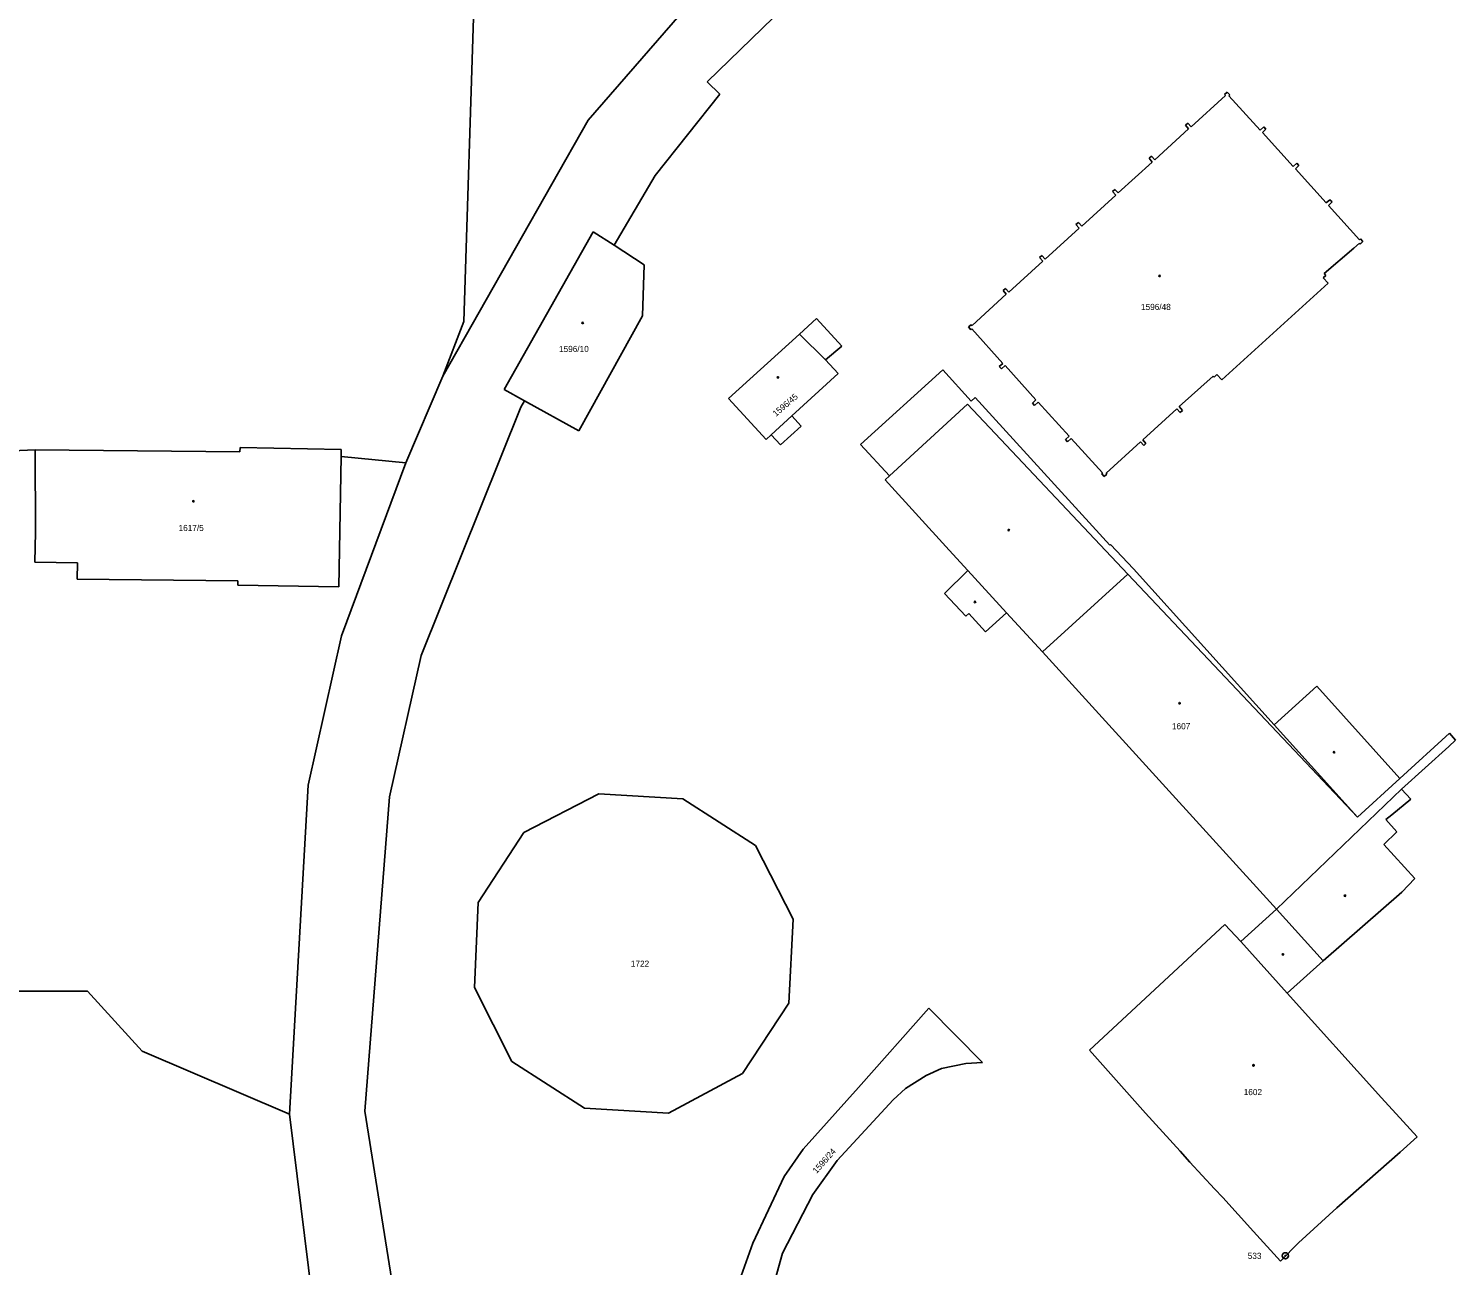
# Model space of a CAD drawing. Extents: x -762761 to -760936, y -1154749 to -1152377.
# Drawn here: x -762540.2 to -762366.3, y -1152807.9 to -1152657.2 of the extents above; entities that cross this region are included whole.
import ezdxf

# ---------------------------------------------------------------- set-up
doc = ezdxf.new("R2010")
doc.units = 0
for name, color, linetype in [('NTL_VÝŠKA', 7, 'Continuous'), ('NTL_ZNAČKA', 7, 'Continuous'), ('NTL_ČÍSLO', 7, 'Continuous'), ('PKO_VÝŠKA', 7, 'Continuous'), ('PKO_ČÍSLO', 7, 'Continuous'), ('PZS_POL_ČÍSLO', 7, 'Continuous'), ('ZP_KÓTY', 7, 'Continuous')]:
    doc.layers.add(name, color=color, linetype=linetype)

msp = doc.modelspace()

# ---------------------------------------------------------------- linework, layer by layer
at = {"layer": 'NTL_VÝŠKA'}
for p, q in [((-762446.26, -1152694.38), (-762443.07, -1152697.52)), ((-762425.8, -1152702.94), (-762435.29, -1152711.67)), ((-762425.8, -1152702.94), (-762406.26, -1152723.62)), ((-762447.19, -1152704.36), (-762449.7, -1152706.66)), ((-762425.74, -1152723.19), (-762421.03, -1152728.33)), ((-762416.67, -1152733.1), (-762406.26, -1152723.62)), ((-762406.26, -1152723.62), (-762378.27, -1152753.23)), ((-762378.27, -1152753.23), (-762388.45, -1152741.99)), ((-762373.11, -1152748.52), (-762378.27, -1152753.23)), ((-762388.13, -1152764.44), (-762372.91, -1152749.82)), ((-762382.45, -1152770.73), (-762388.13, -1152764.44))]:
    msp.add_line(p, q, dxfattribs=at)
at = {"layer": 'NTL_ZNAČKA'}
for p, q in [((-762483.9, -1152590.32), (-762487.15, -1152692.86)), ((-762452.83, -1152646.28), (-762472.01, -1152668.31)), ((-762449.4, -1152655.83), (-762457.48, -1152663.67)), ((-762457.48, -1152663.67), (-762455.94, -1152665.15)), ((-762455.94, -1152665.15), (-762463.84, -1152675.06)), ((-762394.37, -1152665.32), (-762398.54, -1152669.12)), ((-762394.14, -1152664.93), (-762394.47, -1152665.21)), ((-762394.47, -1152665.21), (-762394.37, -1152665.32)), ((-762393.84, -1152665.25), (-762394.14, -1152664.93)), ((-762393.95, -1152665.35), (-762393.84, -1152665.25)), ((-762390.13, -1152669.53), (-762393.95, -1152665.35)), ((-762472.01, -1152668.31), (-762489.68, -1152699.53)), ((-762398.85, -1152669.38), (-762402.98, -1152673.15)), ((-762398.95, -1152668.69), (-762399.24, -1152668.93)), ((-762399.24, -1152668.93), (-762398.85, -1152669.38)), ((-762398.54, -1152669.12), (-762398.95, -1152668.69)), ((-762389.69, -1152669.13), (-762390.13, -1152669.53)), ((-762389.87, -1152669.82), (-762389.43, -1152669.41)), ((-762389.43, -1152669.41), (-762389.69, -1152669.13)), ((-762386.12, -1152673.97), (-762389.87, -1152669.82)), ((-762403.38, -1152672.72), (-762403.67, -1152672.96)), ((-762403.67, -1152672.96), (-762403.29, -1152673.42)), ((-762402.98, -1152673.15), (-762403.38, -1152672.72)), ((-762403.29, -1152673.42), (-762407.42, -1152677.19)), ((-762385.67, -1152673.58), (-762386.12, -1152673.97)), ((-762385.85, -1152674.27), (-762385.41, -1152673.86)), ((-762382.08, -1152678.41), (-762385.85, -1152674.27)), ((-762385.41, -1152673.86), (-762385.67, -1152673.58)), ((-762463.84, -1152675.06), (-762468.82, -1152683.56)), ((-762407.73, -1152677.45), (-762411.87, -1152681.22)), ((-762407.83, -1152676.76), (-762408.12, -1152677)), ((-762408.12, -1152677), (-762407.73, -1152677.45)), ((-762407.42, -1152677.19), (-762407.83, -1152676.76)), ((-762381.65, -1152678.01), (-762382.08, -1152678.41)), ((-762381.38, -1152678.29), (-762381.65, -1152678.01)), ((-762381.81, -1152678.71), (-762381.38, -1152678.29)), ((-762378.02, -1152682.9), (-762381.81, -1152678.71)), ((-762412.18, -1152681.48), (-762416.32, -1152685.25)), ((-762412.28, -1152680.79), (-762412.57, -1152681.04)), ((-762412.57, -1152681.04), (-762412.18, -1152681.48)), ((-762411.87, -1152681.22), (-762412.28, -1152680.79)), ((-762482.24, -1152701.14), (-762471.39, -1152681.91)), ((-762471.39, -1152681.91), (-762468.82, -1152683.56)), ((-762378.74, -1152683.92), (-762378.04, -1152683.31)), ((-762378.04, -1152683.31), (-762377.95, -1152683.41)), ((-762377.9, -1152682.8), (-762378.02, -1152682.9)), ((-762377.95, -1152683.41), (-762377.62, -1152683.11)), ((-762377.62, -1152683.11), (-762377.9, -1152682.8)), ((-762468.82, -1152683.56), (-762465.15, -1152685.93)), ((-762416.72, -1152684.81), (-762417.02, -1152685.06)), ((-762417.02, -1152685.06), (-762416.63, -1152685.52)), ((-762416.32, -1152685.25), (-762416.72, -1152684.81)), ((-762382.33, -1152687.01), (-762378.74, -1152683.92)), ((-762465.15, -1152685.93), (-762465.37, -1152692.18)), ((-762416.63, -1152685.52), (-762420.76, -1152689.28)), ((-762394.82, -1152699.95), (-762381.86, -1152688.18)), ((-762382.47, -1152687.54), (-762382.13, -1152687.24)), ((-762381.86, -1152688.18), (-762382.47, -1152687.54)), ((-762382.13, -1152687.24), (-762382.33, -1152687.01)), ((-762421.07, -1152689.54), (-762425.23, -1152693.35)), ((-762421.16, -1152688.83), (-762421.46, -1152689.09)), ((-762421.46, -1152689.09), (-762421.07, -1152689.54)), ((-762420.76, -1152689.28), (-762421.16, -1152688.83)), ((-762487.15, -1152692.86), (-762489.68, -1152699.53)), ((-762465.37, -1152692.18), (-762473.14, -1152706.19)), ((-762446.26, -1152694.38), (-762444.18, -1152692.48)), ((-762444.18, -1152692.48), (-762441.09, -1152695.84)), ((-762425.34, -1152693.24), (-762425.67, -1152693.52)), ((-762425.67, -1152693.52), (-762425.39, -1152693.85)), ((-762425.39, -1152693.85), (-762425.26, -1152693.76)), ((-762425.23, -1152693.35), (-762425.34, -1152693.24)), ((-762425.26, -1152693.76), (-762421.48, -1152697.95)), ((-762454.88, -1152702.24), (-762446.26, -1152694.38)), ((-762441.09, -1152695.84), (-762443.07, -1152697.52)), ((-762443.07, -1152697.52), (-762441.54, -1152699.2)), ((-762428.78, -1152698.75), (-762438.83, -1152707.85)), ((-762425.34, -1152702.54), (-762428.78, -1152698.75)), ((-762421.48, -1152697.95), (-762421.91, -1152698.35)), ((-762421.91, -1152698.35), (-762421.65, -1152698.63)), ((-762421.65, -1152698.63), (-762421.21, -1152698.23)), ((-762421.21, -1152698.23), (-762417.46, -1152702.38)), ((-762489.68, -1152699.53), (-762494.2, -1152710.06)), ((-762441.54, -1152699.2), (-762447.19, -1152704.36)), ((-762399.99, -1152703.22), (-762395.86, -1152699.5)), ((-762395.86, -1152699.5), (-762395.76, -1152699.62)), ((-762395.76, -1152699.62), (-762395.43, -1152699.3)), ((-762395.43, -1152699.3), (-762394.82, -1152699.95)), ((-762479.75, -1152702.52), (-762482.24, -1152701.14)), ((-762480.19, -1152703.28), (-762479.75, -1152702.52)), ((-762473.14, -1152706.19), (-762479.75, -1152702.52)), ((-762450.31, -1152707.21), (-762454.88, -1152702.24)), ((-762424.84, -1152702.12), (-762425.34, -1152702.54)), ((-762408.46, -1152720.09), (-762424.84, -1152702.12)), ((-762417.46, -1152702.38), (-762417.88, -1152702.79)), ((-762492.32, -1152733.53), (-762480.19, -1152703.28)), ((-762417.88, -1152702.79), (-762417.61, -1152703.07)), ((-762417.61, -1152703.07), (-762417.18, -1152702.67)), ((-762417.18, -1152702.67), (-762413.42, -1152706.84)), ((-762404.44, -1152707.25), (-762400.3, -1152703.49)), ((-762400.3, -1152703.49), (-762399.9, -1152703.94)), ((-762399.61, -1152703.68), (-762399.99, -1152703.22)), ((-762399.9, -1152703.94), (-762399.61, -1152703.68)), ((-762446.06, -1152705.59), (-762448.58, -1152707.88)), ((-762447.19, -1152704.36), (-762446.06, -1152705.59)), ((-762449.7, -1152706.66), (-762450.31, -1152707.21)), ((-762448.58, -1152707.88), (-762449.7, -1152706.66)), ((-762413.42, -1152706.84), (-762413.84, -1152707.24)), ((-762413.84, -1152707.24), (-762413.59, -1152707.51)), ((-762413.59, -1152707.51), (-762413.14, -1152707.12)), ((-762413.14, -1152707.12), (-762409.35, -1152711.3)), ((-762408.91, -1152711.32), (-762404.73, -1152707.52)), ((-762404.73, -1152707.52), (-762404.31, -1152707.95)), ((-762404.05, -1152707.71), (-762404.44, -1152707.25)), ((-762404.31, -1152707.95), (-762404.05, -1152707.71)), ((-762539.34, -1152708.5), (-762546.77, -1152708.77)), ((-762514.4, -1152708.72), (-762539.34, -1152708.5)), ((-762539.34, -1152708.5), (-762539.32, -1152718.51)), ((-762514.39, -1152708.22), (-762514.4, -1152708.72)), ((-762502.07, -1152708.43), (-762514.39, -1152708.22)), ((-762502.38, -1152725.17), (-762502.09, -1152709.28)), ((-762502.09, -1152709.28), (-762502.07, -1152708.43)), ((-762494.2, -1152710.06), (-762502.09, -1152709.28)), ((-762438.83, -1152707.85), (-762435.29, -1152711.67)), ((-762502.04, -1152731.13), (-762494.2, -1152710.06)), ((-762435.8, -1152712.14), (-762435.29, -1152711.67)), ((-762428.02, -1152720.7), (-762435.8, -1152712.14)), ((-762409.35, -1152711.3), (-762409.44, -1152711.4)), ((-762409.44, -1152711.4), (-762409.14, -1152711.72)), ((-762409.14, -1152711.72), (-762408.83, -1152711.44)), ((-762408.83, -1152711.44), (-762408.91, -1152711.32)), ((-762539.32, -1152718.51), (-762539.38, -1152722.19)), ((-762425.74, -1152723.19), (-762428.02, -1152720.7)), ((-762408.36, -1152720.01), (-762408.46, -1152720.09)), ((-762405.58, -1152723), (-762408.36, -1152720.01)), ((-762539.38, -1152722.19), (-762534.2, -1152722.27)), ((-762534.2, -1152722.27), (-762534.23, -1152724.25)), ((-762425.74, -1152723.19), (-762428.57, -1152725.99)), ((-762388.45, -1152741.99), (-762405.58, -1152723)), ((-762534.23, -1152724.25), (-762514.66, -1152724.44)), ((-762514.66, -1152724.44), (-762514.67, -1152724.97)), ((-762514.67, -1152724.97), (-762502.38, -1152725.17)), ((-762428.57, -1152725.99), (-762426, -1152728.75)), ((-762426, -1152728.75), (-762425.64, -1152728.42)), ((-762425.64, -1152728.42), (-762423.58, -1152730.67)), ((-762423.58, -1152730.67), (-762421.03, -1152728.33)), ((-762416.67, -1152733.1), (-762421.03, -1152728.33)), ((-762506.09, -1152749.33), (-762502.04, -1152731.13)), ((-762492.32, -1152733.53), (-762496.17, -1152750.77)), ((-762416.67, -1152733.1), (-762411, -1152739.29)), ((-762383.24, -1152737.28), (-762388.45, -1152741.99)), ((-762373.11, -1152748.52), (-762383.24, -1152737.28)), ((-762411, -1152739.29), (-762388.13, -1152764.44)), ((-762367.09, -1152743.02), (-762373.11, -1152748.52)), ((-762367.17, -1152744.61), (-762366.35, -1152743.86)), ((-762366.35, -1152743.86), (-762367.09, -1152743.02)), ((-762372.91, -1152749.82), (-762367.17, -1152744.61)), ((-762508.36, -1152789.42), (-762506.09, -1152749.33)), ((-762496.17, -1152750.77), (-762499.2, -1152789.04)), ((-762470.69, -1152750.4), (-762479.81, -1152755.1)), ((-762460.47, -1152751), (-762470.69, -1152750.4)), ((-762460.47, -1152751), (-762451.62, -1152756.7)), ((-762374.12, -1152752.96), (-762371.79, -1152751.06)), ((-762371.79, -1152751.06), (-762372.91, -1152749.82)), ((-762374.82, -1152753.54), (-762374.12, -1152752.96)), ((-762373.51, -1152755.04), (-762374.82, -1152753.54)), ((-762479.81, -1152755.1), (-762485.39, -1152763.63)), ((-762375.07, -1152756.55), (-762373.51, -1152755.04)), ((-762451.62, -1152756.7), (-762447.02, -1152765.68)), ((-762371.31, -1152760.71), (-762375.07, -1152756.55)), ((-762372.87, -1152762.36), (-762371.31, -1152760.71)), ((-762382.45, -1152770.73), (-762372.87, -1152762.36)), ((-762485.39, -1152763.63), (-762485.82, -1152774)), ((-762388.13, -1152764.44), (-762392.51, -1152768.38)), ((-762447.02, -1152765.68), (-762447.54, -1152775.89)), ((-762410.91, -1152781.62), (-762394.44, -1152766.33)), ((-762394.44, -1152766.33), (-762392.51, -1152768.38)), ((-762392.51, -1152768.38), (-762386.84, -1152774.68)), ((-762386.84, -1152774.68), (-762382.45, -1152770.73)), ((-762532.99, -1152774.42), (-762542.3, -1152774.42)), ((-762526.31, -1152781.74), (-762532.99, -1152774.42)), ((-762485.82, -1152774), (-762481.28, -1152783)), ((-762386.84, -1152774.68), (-762375.36, -1152787.41)), ((-762447.54, -1152775.89), (-762453.19, -1152784.48)), ((-762439.08, -1152786.17), (-762430.49, -1152776.49)), ((-762430.49, -1152776.49), (-762423.95, -1152783.13)), ((-762508.36, -1152789.42), (-762526.31, -1152781.74)), ((-762404.12, -1152789.3), (-762410.91, -1152781.62)), ((-762481.28, -1152783), (-762472.43, -1152788.7)), ((-762428.97, -1152783.85), (-762430.82, -1152784.7)), ((-762426, -1152783.24), (-762428.97, -1152783.85)), ((-762423.95, -1152783.13), (-762426, -1152783.24)), ((-762462.21, -1152789.3), (-762453.19, -1152784.48)), ((-762430.82, -1152784.7), (-762433.34, -1152786.3)), ((-762445.79, -1152793.67), (-762439.08, -1152786.17)), ((-762434.84, -1152787.68), (-762441.66, -1152795.08)), ((-762433.34, -1152786.3), (-762434.84, -1152787.68)), ((-762375.36, -1152787.41), (-762372.72, -1152790.32)), ((-762508.36, -1152789.42), (-762504.64, -1152819.5)), ((-762499.2, -1152789.04), (-762495.62, -1152811.48)), ((-762472.43, -1152788.7), (-762462.21, -1152789.3)), ((-762399.9, -1152793.94), (-762404.12, -1152789.3)), ((-762372.72, -1152790.32), (-762371.03, -1152792.19)), ((-762371.03, -1152792.19), (-762373.07, -1152794.05)), ((-762448.1, -1152797.01), (-762445.79, -1152793.67)), ((-762398.69, -1152795.27), (-762399.9, -1152793.94)), ((-762373.07, -1152794.05), (-762380.8, -1152800.84)), ((-762441.66, -1152795.08), (-762444.61, -1152799.19)), ((-762395.72, -1152798.53), (-762398.69, -1152795.27)), ((-762451.93, -1152805.15), (-762448.1, -1152797.01)), ((-762444.61, -1152799.19), (-762448.3, -1152806.34)), ((-762394.69, -1152799.57), (-762395.72, -1152798.53)), ((-762390.93, -1152803.73), (-762394.69, -1152799.57)), ((-762380.8, -1152800.84), (-762385.46, -1152805.08)), ((-762387.68, -1152807.32), (-762390.93, -1152803.73)), ((-762385.46, -1152805.08), (-762387.68, -1152807.32)), ((-762453.95, -1152810.83), (-762451.93, -1152805.15)), ((-762448.3, -1152806.34), (-762450.74, -1152815.01))]:
    msp.add_line(p, q, dxfattribs=at)
at = {"layer": 'NTL_ČÍSLO'}
for centre in [(-762402.39, -1152687.3), (-762472.66, -1152693.02), (-762448.88, -1152699.66), (-762520.07, -1152714.75), (-762420.76, -1152718.26), (-762424.87, -1152727.02), (-762399.95, -1152739.35), (-762381.13, -1152745.32), (-762379.81, -1152762.8), (-762387.37, -1152769.96), (-762390.95, -1152783.47)]:
    msp.add_circle(centre, 0.0875, dxfattribs=at)
at = {"layer": 'PKO_ČÍSLO'}
for radius in [0.375, 0.05]:
    msp.add_circle((-762387.07, -1152806.67), radius, dxfattribs=at)

# ---------------------------------------------------------------- texts
at = {"layer": 'PKO_VÝŠKA'}
msp.add_text('1722', height=0.75, dxfattribs=at).set_placement((-762466.79, -1152771.46))
msp.add_text('1596/24', height=0.75, rotation=48.4149, dxfattribs=at).set_placement((-762444.16, -1152796.71))
at = {"layer": 'PZS_POL_ČÍSLO'}
msp.add_text('533', height=0.75, dxfattribs=at).set_placement((-762391.65, -1152807.05))
at = {"layer": 'ZP_KÓTY'}
for s, p in [('1596/48', (-762404.65, -1152691.45)), ('1596/10', (-762475.54, -1152696.57)), ('1617/5', (-762521.88, -1152718.38)), ('1607', (-762400.88, -1152742.53)), ('1602', (-762392.14, -1152787.1))]:
    msp.add_text(s, height=0.75, dxfattribs=at).set_placement(p)
msp.add_text('1596/45', height=0.75, rotation=40.5081, dxfattribs=at).set_placement((-762449.12, -1152704.48))

doc.saveas('drawing.dxf')
